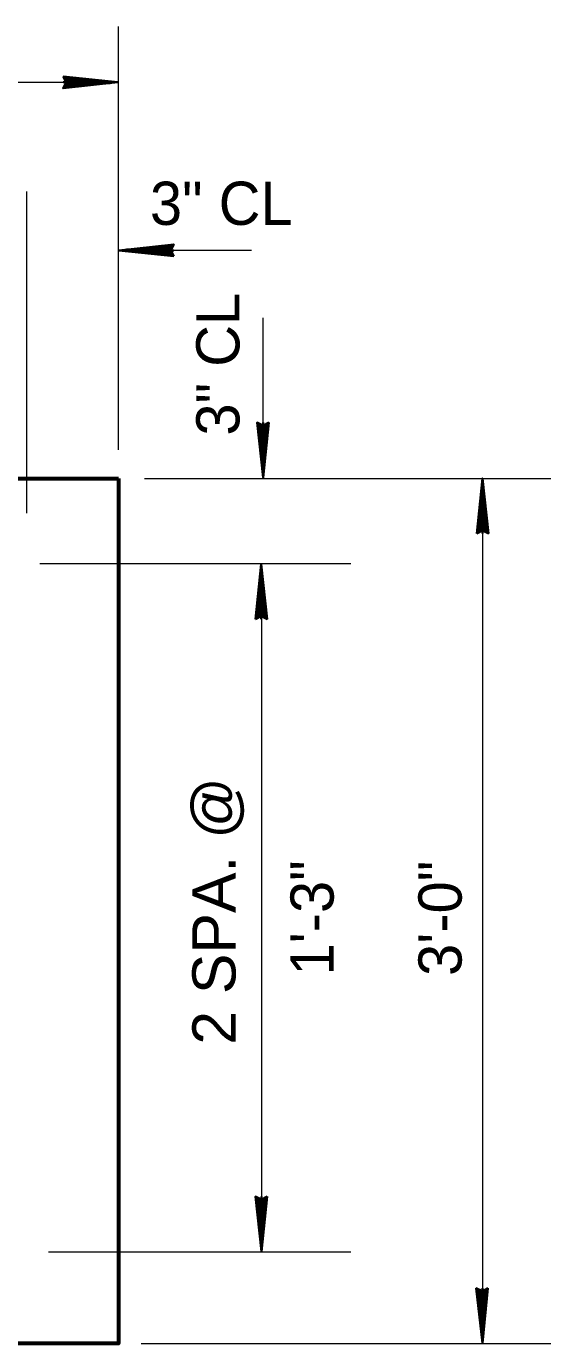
# Model space of a CAD drawing. Extents: x 6.34 to 9.53, y -1.46 to 0.53.
# Drawn here: x 7.2845 to 7.3856, y 0.0454 to 0.2992 of the extents above; entities that cross this region are included whole.
import ezdxf

# ---------------------------------------------------------------- set-up
doc = ezdxf.new("R2010")
doc.units = 0
doc.header["$LTSCALE"] = 0.0033
doc.layers.add('1', color=7, linetype='Continuous', lineweight=40)

msp = doc.modelspace()

# ---------------------------------------------------------------- linework, layer by layer
at = {"layer": '1', "lineweight": 13}
for p, q in [((7.30225, 0.217583), (7.30225, 0.299167)), ((6.718833, 0.288417), (7.301167, 0.288417)), ((7.284583, 0.205417), (7.284583, 0.267333)), ((7.312167, 0.256083), (7.327917, 0.256083)), ((7.330167, 0.222167), (7.330167, 0.243)), ((7.30725, 0.212083), (7.385583, 0.212083)), ((7.372417, 0.211417), (7.372417, 0.045417)), ((7.287083, 0.195667), (7.347083, 0.195667)), ((7.329833, 0.193583), (7.329833, 0.064)), ((7.28875, 0.063083), (7.347083, 0.063083)), ((7.30225, 0.045417), (7.302583, 0.045417)), ((7.306667, 0.045417), (7.385583, 0.045417))]:
    msp.add_line(p, q, dxfattribs=at)
at = {"layer": '1', "lineweight": 35}
for p, q in [((7.291833, 0.289417), (7.299667, 0.2885)), ((7.291833, 0.289417), (7.299667, 0.2885)), ((7.291833, 0.289333), (7.299667, 0.2885)), ((7.291583, 0.288417), (7.302167, 0.288417)), ((7.29175, 0.28775), (7.299083, 0.2885)), ((7.291833, 0.28925), (7.299667, 0.288417)), ((7.291833, 0.28925), (7.299667, 0.28825)), ((7.291833, 0.287583), (7.299167, 0.288417)), ((7.291833, 0.2875), (7.299167, 0.28825)), ((7.291833, 0.287333), (7.299167, 0.288167)), ((7.312667, 0.257083), (7.305333, 0.25625)), ((7.312667, 0.256917), (7.305333, 0.256167)), ((7.312667, 0.256833), (7.305333, 0.256)), ((7.31275, 0.256667), (7.305417, 0.255917)), ((7.312917, 0.256), (7.302333, 0.256)), ((7.312667, 0.255167), (7.304833, 0.256167)), ((7.312667, 0.255167), (7.304833, 0.256)), ((7.312667, 0.255), (7.304833, 0.255917)), ((7.312667, 0.255), (7.304833, 0.255917)), ((7.312667, 0.255083), (7.304833, 0.255917)), ((7.329083, 0.222583), (7.329917, 0.21525)), ((7.32925, 0.222583), (7.33, 0.21525)), ((7.329333, 0.222583), (7.330167, 0.21525)), ((7.3295, 0.222667), (7.33025, 0.215333)), ((7.331, 0.222583), (7.33, 0.21475)), ((7.330167, 0.222833), (7.330167, 0.21225)), ((7.331, 0.222583), (7.330167, 0.21475)), ((7.331167, 0.222583), (7.33025, 0.21475)), ((7.331167, 0.222583), (7.33025, 0.21475)), ((7.331083, 0.222583), (7.33025, 0.21475)), ((7.372417, 0.2015), (7.372417, 0.212083)), ((7.371417, 0.20175), (7.372333, 0.209583)), ((7.371417, 0.20175), (7.372333, 0.209583)), ((7.3715, 0.20175), (7.372333, 0.209583)), ((7.371583, 0.20175), (7.372417, 0.209583)), ((7.371583, 0.20175), (7.372583, 0.209583)), ((7.373083, 0.201667), (7.372333, 0.209)), ((7.37325, 0.20175), (7.372417, 0.209083)), ((7.373333, 0.20175), (7.372583, 0.209083)), ((7.3735, 0.20175), (7.372667, 0.209083)), ((7.32975, 0.185), (7.32975, 0.195583)), ((7.32875, 0.18525), (7.329667, 0.193083)), ((7.32875, 0.18525), (7.329667, 0.193083)), ((7.328833, 0.18525), (7.329667, 0.193083)), ((7.328917, 0.18525), (7.32975, 0.193083)), ((7.328917, 0.18525), (7.329917, 0.193083)), ((7.330417, 0.185167), (7.329667, 0.1925)), ((7.330583, 0.18525), (7.32975, 0.192583)), ((7.330667, 0.18525), (7.329917, 0.192583)), ((7.330833, 0.18525), (7.33, 0.192583)), ((7.329833, 0.07375), (7.329833, 0.063167)), ((7.32875, 0.0735), (7.329583, 0.066167)), ((7.328917, 0.0735), (7.329667, 0.066167)), ((7.329, 0.0735), (7.329833, 0.066167)), ((7.329167, 0.073583), (7.329917, 0.06625)), ((7.330667, 0.0735), (7.329667, 0.065667)), ((7.330667, 0.0735), (7.329833, 0.065667)), ((7.330833, 0.0735), (7.329917, 0.065667)), ((7.330833, 0.0735), (7.329917, 0.065667)), ((7.33075, 0.0735), (7.329917, 0.065667)), ((7.371333, 0.055833), (7.372167, 0.0485)), ((7.3715, 0.055833), (7.37225, 0.0485)), ((7.371583, 0.055833), (7.372417, 0.0485)), ((7.37175, 0.055917), (7.3725, 0.048583)), ((7.37325, 0.055833), (7.37225, 0.048)), ((7.372417, 0.056083), (7.372417, 0.0455)), ((7.37325, 0.055833), (7.372417, 0.048)), ((7.373417, 0.055833), (7.3725, 0.048)), ((7.373417, 0.055833), (7.3725, 0.048)), ((7.373333, 0.055833), (7.3725, 0.048))]:
    msp.add_line(p, q, dxfattribs=at)
at = {"layer": '1', "lineweight": 60}
msp.add_line((6.718917, 0.212083), (7.30225, 0.212083), dxfattribs=at)
at = {"layer": '1', "lineweight": 35}
for points in [[(7.291583, 0.2895), (7.302167, 0.288417), (7.291583, 0.28725), (7.292167, 0.288417)], [(7.292333, 0.2885), (7.297, 0.288583), (7.297, 0.2885), (7.296083, 0.2885), (7.292333, 0.288583), (7.295333, 0.288667), (7.292167, 0.28875), (7.294417, 0.288833), (7.292167, 0.288917), (7.295667, 0.288667), (7.300333, 0.2885), (7.299417, 0.28825), (7.300667, 0.28825), (7.292333, 0.28825), (7.29475, 0.288083), (7.292167, 0.288083), (7.2975, 0.2885), (7.292167, 0.287833)], [(7.312917, 0.254917), (7.302333, 0.256), (7.312917, 0.257167), (7.312333, 0.256)], [(7.312167, 0.255917), (7.3075, 0.255833), (7.3075, 0.255917), (7.308417, 0.255917), (7.312167, 0.255833), (7.309167, 0.25575), (7.312333, 0.255667), (7.310083, 0.255583), (7.312333, 0.2555), (7.308833, 0.25575), (7.304167, 0.255917), (7.305083, 0.256167), (7.303833, 0.256167), (7.312167, 0.256167), (7.30975, 0.256333), (7.312333, 0.256333), (7.307, 0.255917), (7.312333, 0.256583)], [(7.33125, 0.222833), (7.330167, 0.21225), (7.329, 0.222833), (7.330167, 0.22225)], [(7.33025, 0.222083), (7.330333, 0.217417), (7.33025, 0.217417), (7.33025, 0.218333), (7.330333, 0.222083), (7.330417, 0.219083), (7.3305, 0.22225), (7.330583, 0.22), (7.330667, 0.22225), (7.330417, 0.21875), (7.33025, 0.214083), (7.33, 0.215), (7.33, 0.21375), (7.33, 0.222083), (7.329833, 0.219667), (7.329833, 0.22225), (7.33025, 0.216917), (7.329583, 0.22225)], [(7.371333, 0.2015), (7.372417, 0.212083), (7.373583, 0.2015), (7.372417, 0.202083)], [(7.372333, 0.20225), (7.37225, 0.206917), (7.372333, 0.206917), (7.372333, 0.206), (7.37225, 0.20225), (7.372167, 0.20525), (7.372083, 0.202083), (7.372, 0.204333), (7.371917, 0.202083), (7.372167, 0.205583), (7.372333, 0.21025), (7.372583, 0.209333), (7.372583, 0.210583), (7.372583, 0.20225), (7.37275, 0.204667), (7.37275, 0.202083), (7.372333, 0.207417), (7.373, 0.202083)], [(7.328667, 0.185), (7.32975, 0.195583), (7.330917, 0.185), (7.32975, 0.185583)], [(7.329667, 0.18575), (7.329583, 0.190417), (7.329667, 0.190417), (7.329667, 0.1895), (7.329583, 0.18575), (7.3295, 0.18875), (7.329417, 0.185583), (7.329333, 0.187833), (7.32925, 0.185583), (7.3295, 0.189083), (7.329667, 0.19375), (7.329917, 0.192833), (7.329917, 0.194083), (7.329917, 0.18575), (7.330083, 0.188167), (7.330083, 0.185583), (7.329667, 0.190917), (7.330333, 0.185583)], [(7.330917, 0.07375), (7.329833, 0.063167), (7.328667, 0.07375), (7.329833, 0.073167)], [(7.329917, 0.073), (7.33, 0.068333), (7.329917, 0.068333), (7.329917, 0.06925), (7.33, 0.073), (7.330083, 0.07), (7.330167, 0.073167), (7.33025, 0.070917), (7.330333, 0.073167), (7.330083, 0.069667), (7.329917, 0.065), (7.329667, 0.065917), (7.329667, 0.064667), (7.329667, 0.073), (7.3295, 0.070583), (7.3295, 0.073167), (7.329917, 0.067833), (7.32925, 0.073167)], [(7.3735, 0.056083), (7.372417, 0.0455), (7.37125, 0.056083), (7.372417, 0.0555)], [(7.3725, 0.055333), (7.372583, 0.050667), (7.3725, 0.050667), (7.3725, 0.051583), (7.372583, 0.055333), (7.372667, 0.052333), (7.37275, 0.0555), (7.372833, 0.05325), (7.372917, 0.0555), (7.372667, 0.052), (7.3725, 0.047333), (7.37225, 0.04825), (7.37225, 0.047), (7.37225, 0.055333), (7.372083, 0.052917), (7.372083, 0.0555), (7.3725, 0.050167), (7.371833, 0.0555)]]:
    msp.add_lwpolyline(points, close=True, dxfattribs=at)
for points in [[(7.292333, 0.2885), (7.291917, 0.28925), (7.292167, 0.289), (7.292333, 0.288667), (7.292583, 0.28875), (7.292417, 0.289083), (7.29225, 0.288333), (7.292083, 0.287833), (7.291833, 0.287417)], [(7.312167, 0.255917), (7.312583, 0.255167), (7.312333, 0.255417), (7.312167, 0.25575), (7.311917, 0.255667), (7.312083, 0.255333), (7.31225, 0.256083), (7.312417, 0.256583), (7.312667, 0.257)], [(7.33025, 0.222083), (7.331, 0.2225), (7.33075, 0.22225), (7.330417, 0.222083), (7.3305, 0.221833), (7.330833, 0.222), (7.330083, 0.222167), (7.329583, 0.222333), (7.329167, 0.222583)], [(7.372333, 0.20225), (7.371583, 0.201833), (7.371833, 0.202083), (7.372167, 0.20225), (7.372083, 0.2025), (7.37175, 0.202333), (7.3725, 0.202167), (7.373, 0.202), (7.373417, 0.20175)], [(7.329667, 0.18575), (7.328917, 0.185333), (7.329167, 0.185583), (7.3295, 0.18575), (7.329417, 0.186), (7.329083, 0.185833), (7.329833, 0.185667), (7.330333, 0.1855), (7.33075, 0.18525)], [(7.329917, 0.073), (7.330667, 0.073417), (7.330417, 0.073167), (7.330083, 0.073), (7.330167, 0.07275), (7.3305, 0.072917), (7.32975, 0.073083), (7.32925, 0.07325), (7.328833, 0.0735)], [(7.3725, 0.055333), (7.37325, 0.05575), (7.373, 0.0555), (7.372667, 0.055333), (7.37275, 0.055083), (7.373083, 0.05525), (7.372333, 0.055417), (7.371833, 0.055583), (7.371417, 0.055833)]]:
    msp.add_lwpolyline(points, dxfattribs=at)
at = {"layer": '1', "lineweight": 60}
msp.add_lwpolyline([(7.30225, 0.212083), (7.30225, 0.045417), (6.718917, 0.045417), (6.718917, 0.212083)], dxfattribs=at)

# ---------------------------------------------------------------- texts
at = {"layer": '1'}
msp.add_text('3" CL', height=0.008334, dxfattribs=at).set_placement((7.308333, 0.260917))
for s, height, p in [('3" CL', 0.008334, (7.325583, 0.220333)), ('1\'-3"', 0.008334, (7.34375, 0.116333)), ('3\'-0"', 0.008333, (7.368417, 0.11625))]:
    msp.add_text(s, height=height, rotation=90, dxfattribs=at).set_placement(p)
at = {"layer": '1', "width": 1.05}
msp.add_text('2 SPA. @ ', height=0.008334, rotation=90, dxfattribs=at).set_placement((7.324833, 0.103))

doc.saveas('drawing.dxf')
